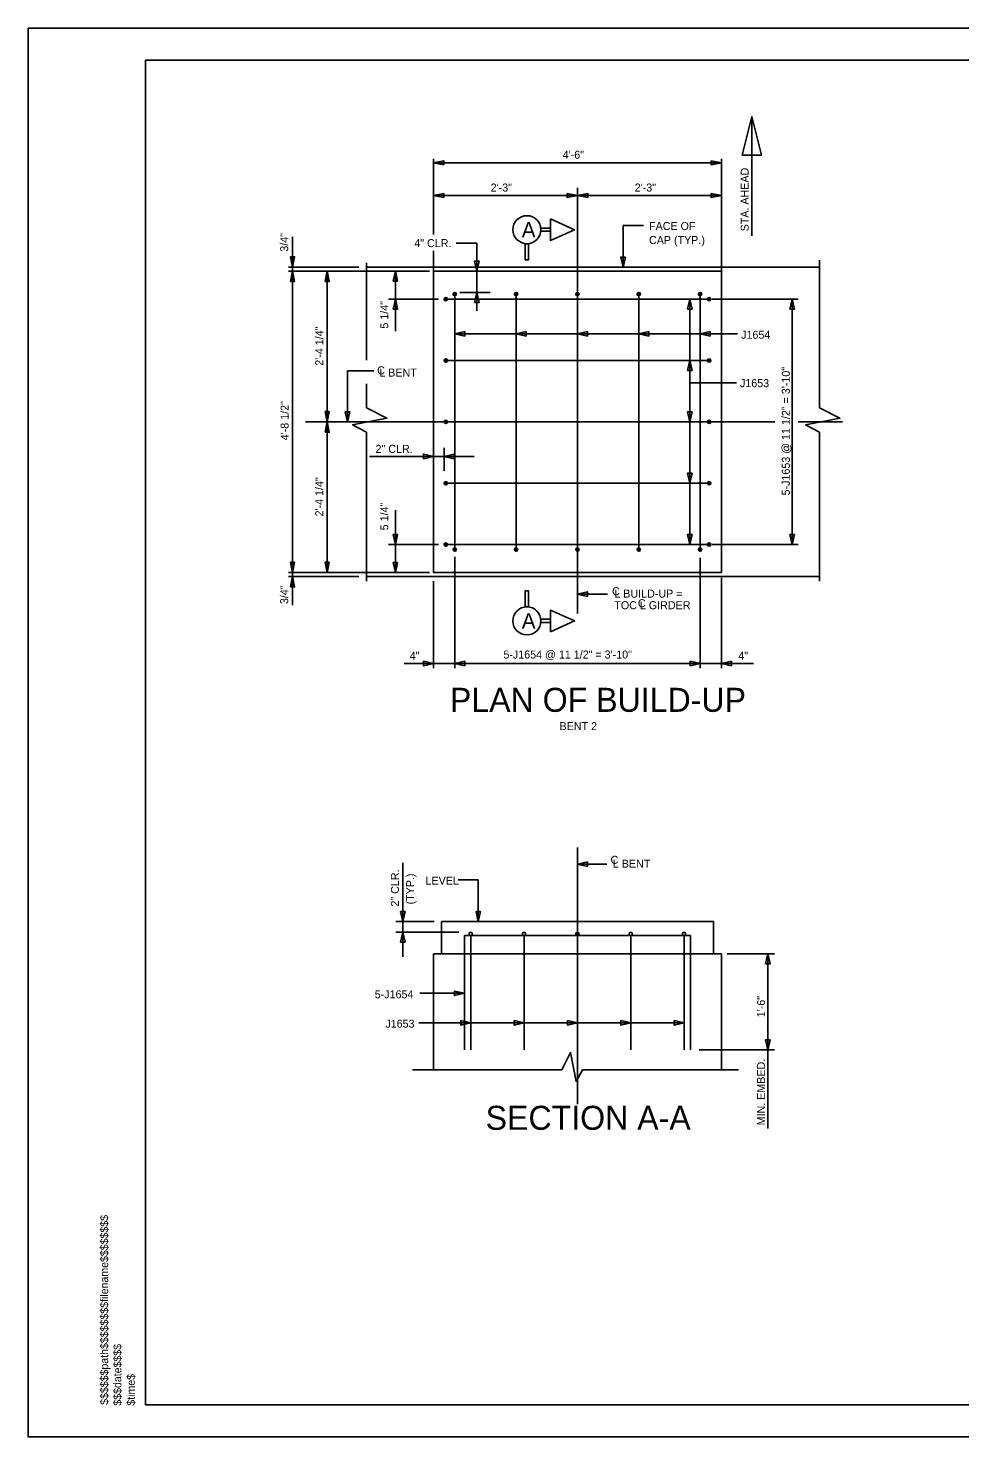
# Model space of a CAD drawing. Extents: x 1970675.2 to 1970711.3, y 796145.2 to 796167.2.
# Drawn here: x 1970675.24 to 1970689.79, y 796145.25 to 796167.25 of the extents above; entities that cross this region are included whole.
import ezdxf

# ---------------------------------------------------------------- set-up
doc = ezdxf.new("R2010")
doc.units = 0
for name, color, linetype in [('BR_AUTO DIMENSION', 7, 'Continuous'), ('BR_BORDER LINES', 7, 'Continuous'), ('BR_CENTER LINES', 7, 'Continuous'), ('BR_CONCRETE', 7, 'Continuous'), ('BR_REBAR', 7, 'Continuous'), ('BR_TEXT', 7, 'Continuous'), ('Default', 7, 'Continuous'), ('Level 31', 7, 'Continuous'), ('RD_SHT_ID', 7, 'Continuous')]:
    doc.layers.add(name, color=color, linetype=linetype)

msp = doc.modelspace()

# ---------------------------------------------------------------- linework, layer by layer
at = {"layer": 'BR_AUTO DIMENSION'}
for p, q in [((1970686.542, 796165.865), (1970686.542, 796164.002)), ((1970681.566, 796164.025), (1970681.566, 796165.207)), ((1970686.066, 796163.452), (1970686.066, 796165.207)), ((1970681.566, 796165.145), (1970686.066, 796165.145)), ((1970683.816, 796164.751), (1970683.816, 796164.386)), ((1970681.566, 796164.632), (1970683.816, 796164.632)), ((1970686.066, 796164.632), (1970683.816, 796164.632)), ((1970684.53, 796164.165), (1970684.53, 796163.515)), ((1970684.53, 796164.165), (1970684.847, 796164.165)), ((1970679.367, 796163.452), (1970679.367, 796163.985)), ((1970682.246, 796163.89), (1970681.922, 796163.89)), ((1970682.246, 796162.831), (1970682.246, 796163.89)), ((1970681.566, 796163.452), (1970681.566, 796163.771)), ((1970680.402, 796163.515), (1970679.301, 796163.515)), ((1970681.504, 796163.452), (1970679.305, 796163.452)), ((1970679.367, 796158.744), (1970679.367, 796163.452)), ((1970679.909, 796163.452), (1970679.909, 796161.098)), ((1970680.972, 796163.452), (1970680.972, 796162.513)), ((1970681.645, 796163.015), (1970680.865, 796163.015)), ((1970681.978, 796163.119), (1970682.453, 796163.119)), ((1970685.57, 796163.015), (1970685.57, 796159.181)), ((1970685.921, 796163.015), (1970687.264, 796163.015)), ((1970687.172, 796159.181), (1970687.172, 796163.015)), ((1970681.9, 796162.474), (1970686.315, 796162.474)), ((1970680.223, 796161.897), (1970680.223, 796161.098)), ((1970680.635, 796161.897), (1970680.223, 796161.897)), ((1970685.57, 796161.705), (1970686.299, 796161.705)), ((1970679.852, 796161.098), (1970679.988, 796161.098)), ((1970679.909, 796161.098), (1970679.909, 796158.744)), ((1970682.202, 796160.558), (1970680.567, 796160.558)), ((1970681.733, 796160.69), (1970681.733, 796160.334)), ((1970680.972, 796158.744), (1970680.972, 796159.718)), ((1970681.645, 796159.181), (1970680.865, 796159.181)), ((1970685.921, 796159.181), (1970687.264, 796159.181)), ((1970681.9, 796158.988), (1970681.9, 796157.249)), ((1970685.733, 796158.975), (1970685.733, 796157.249)), ((1970680.402, 796158.681), (1970679.301, 796158.681)), ((1970681.504, 796158.744), (1970679.305, 796158.744)), ((1970679.367, 796158.744), (1970679.367, 796158.233)), ((1970681.566, 796158.61), (1970681.566, 796157.249)), ((1970686.066, 796158.661), (1970686.066, 796157.249)), ((1970683.816, 796158.408), (1970684.288, 796158.408)), ((1970681.11, 796157.324), (1970686.568, 796157.324)), ((1970681.088, 796154.21), (1970681.088, 796152.745)), ((1970683.816, 796154.19), (1970684.276, 796154.19)), ((1970681.951, 796153.943), (1970682.268, 796153.943)), ((1970682.268, 796153.943), (1970682.268, 796153.293)), ((1970681.577, 796153.293), (1970680.978, 796153.293)), ((1970681.966, 796153.126), (1970680.978, 796153.126)), ((1970686.154, 796152.792), (1970686.897, 796152.792)), ((1970686.791, 796152.792), (1970686.791, 796150.062)), ((1970682.051, 796152.173), (1970681.356, 796152.173)), ((1970685.483, 796151.714), (1970681.338, 796151.714)), ((1970681.733, 796151.714), (1970681.653, 796151.714)), ((1970682.983, 796151.714), (1970682.903, 796151.714)), ((1970683.816, 796151.714), (1970683.736, 796151.714)), ((1970684.15, 796151.714), (1970684.069, 796151.714)), ((1970684.65, 796151.714), (1970684.569, 796151.714)), ((1970685.483, 796151.714), (1970685.403, 796151.714)), ((1970685.717, 796151.292), (1970686.897, 796151.292))]:
    msp.add_line(p, q, dxfattribs=at)
for points in [[(1970681.729, 796165.113), (1970681.566, 796165.145), (1970681.729, 796165.176)], [(1970685.904, 796165.176), (1970686.066, 796165.145), (1970685.904, 796165.113)], [(1970681.729, 796164.601), (1970681.566, 796164.632), (1970681.729, 796164.664)], [(1970683.654, 796164.664), (1970683.816, 796164.632), (1970683.654, 796164.601)], [(1970683.979, 796164.601), (1970683.816, 796164.632), (1970683.979, 796164.664)], [(1970685.904, 796164.664), (1970686.066, 796164.632), (1970685.904, 796164.601)], [(1970679.336, 796163.677), (1970679.367, 796163.515), (1970679.398, 796163.677)], [(1970684.566, 796163.671), (1970684.53, 796163.515), (1970684.494, 796163.671)], [(1970679.336, 796163.29), (1970679.367, 796163.452), (1970679.398, 796163.29)], [(1970679.878, 796163.29), (1970679.909, 796163.452), (1970679.94, 796163.29)], [(1970681.008, 796163.296), (1970680.972, 796163.452), (1970680.936, 796163.296)], [(1970682.282, 796163.608), (1970682.246, 796163.452), (1970682.21, 796163.608)], [(1970681.008, 796162.859), (1970680.972, 796163.015), (1970680.936, 796162.859)], [(1970682.21, 796162.963), (1970682.246, 796163.119), (1970682.282, 796162.963)], [(1970685.534, 796162.859), (1970685.57, 796163.015), (1970685.606, 796162.859)], [(1970687.136, 796162.859), (1970687.172, 796163.015), (1970687.208, 796162.859)], [(1970682.056, 796162.51), (1970681.9, 796162.474), (1970682.056, 796162.438)], [(1970683.014, 796162.51), (1970682.858, 796162.474), (1970683.014, 796162.438)], [(1970683.972, 796162.51), (1970683.816, 796162.474), (1970683.972, 796162.438)], [(1970684.931, 796162.51), (1970684.775, 796162.474), (1970684.931, 796162.438)], [(1970685.889, 796162.51), (1970685.733, 796162.474), (1970685.889, 796162.438)], [(1970685.534, 796161.9), (1970685.57, 796162.056), (1970685.606, 796161.9)], [(1970679.94, 796161.26), (1970679.909, 796161.098), (1970679.878, 796161.26)], [(1970680.259, 796161.254), (1970680.223, 796161.098), (1970680.187, 796161.254)], [(1970685.606, 796161.254), (1970685.57, 796161.098), (1970685.534, 796161.254)], [(1970679.878, 796160.935), (1970679.909, 796161.098), (1970679.94, 796160.935)], [(1970681.41, 796160.522), (1970681.566, 796160.558), (1970681.41, 796160.594)], [(1970681.889, 796160.594), (1970681.733, 796160.558), (1970681.889, 796160.522)], [(1970685.606, 796160.296), (1970685.57, 796160.14), (1970685.534, 796160.296)], [(1970681.008, 796159.337), (1970680.972, 796159.181), (1970680.936, 796159.337)], [(1970685.606, 796159.337), (1970685.57, 796159.181), (1970685.534, 796159.337)], [(1970687.208, 796159.337), (1970687.172, 796159.181), (1970687.136, 796159.337)], [(1970679.398, 796158.906), (1970679.367, 796158.744), (1970679.336, 796158.906)], [(1970679.94, 796158.906), (1970679.909, 796158.744), (1970679.878, 796158.906)], [(1970681.008, 796158.9), (1970680.972, 796158.744), (1970680.936, 796158.9)], [(1970679.336, 796158.519), (1970679.367, 796158.681), (1970679.398, 796158.519)], [(1970683.972, 796158.372), (1970683.816, 796158.408), (1970683.972, 796158.444)], [(1970681.41, 796157.36), (1970681.566, 796157.324), (1970681.41, 796157.288)], [(1970682.056, 796157.288), (1970681.9, 796157.324), (1970682.056, 796157.36)], [(1970685.577, 796157.36), (1970685.733, 796157.324), (1970685.577, 796157.288)], [(1970686.222, 796157.36), (1970686.066, 796157.324), (1970686.222, 796157.288)], [(1970683.972, 796154.154), (1970683.816, 796154.19), (1970683.972, 796154.226)], [(1970681.124, 796153.449), (1970681.088, 796153.293), (1970681.052, 796153.449)], [(1970682.304, 796153.449), (1970682.268, 796153.293), (1970682.232, 796153.449)], [(1970681.052, 796152.97), (1970681.088, 796153.126), (1970681.124, 796152.97)], [(1970686.755, 796152.636), (1970686.791, 796152.792), (1970686.827, 796152.636)], [(1970681.895, 796152.209), (1970682.051, 796152.173), (1970681.895, 796152.137)], [(1970681.994, 796151.75), (1970682.15, 796151.714), (1970681.994, 796151.678)], [(1970682.827, 796151.75), (1970682.983, 796151.714), (1970682.827, 796151.678)], [(1970683.66, 796151.75), (1970683.816, 796151.714), (1970683.66, 796151.678)], [(1970684.494, 796151.75), (1970684.65, 796151.714), (1970684.494, 796151.678)], [(1970685.327, 796151.75), (1970685.483, 796151.714), (1970685.327, 796151.678)], [(1970686.827, 796151.448), (1970686.791, 796151.292), (1970686.755, 796151.448)]]:
    msp.add_lwpolyline(points, close=True, dxfattribs=at)
at = {"layer": 'BR_BORDER LINES'}
for p, q in [((1970710.736, 796166.746), (1970677.07, 796166.746)), ((1970677.07, 796145.746), (1970677.07, 796166.746)), ((1970677.07, 796145.746), (1970710.736, 796145.746))]:
    msp.add_line(p, q, dxfattribs=at)
at = {"layer": 'BR_CENTER LINES'}
for p, q in [((1970683.816, 796164.632), (1970683.816, 796158.104)), ((1970679.567, 796161.098), (1970686.901, 796161.098)), ((1970687.263, 796161.098), (1970687.959, 796161.098)), ((1970683.816, 796154.451), (1970683.816, 796150.443))]:
    msp.add_line(p, q, dxfattribs=at)
at = {"layer": 'BR_CONCRETE'}
for p, q in [((1970680.522, 796163.515), (1970687.596, 796163.515)), ((1970681.566, 796163.452), (1970681.566, 796158.744)), ((1970681.566, 796163.452), (1970686.066, 796163.452)), ((1970686.066, 796163.452), (1970686.066, 796158.744)), ((1970680.522, 796158.681), (1970687.596, 796158.681)), ((1970681.566, 796158.744), (1970686.066, 796158.744)), ((1970681.691, 796153.293), (1970681.691, 796152.792)), ((1970681.691, 796153.293), (1970685.941, 796153.293)), ((1970685.941, 796153.293), (1970685.941, 796152.792)), ((1970681.566, 796152.792), (1970681.566, 796150.98)), ((1970681.566, 796152.792), (1970686.066, 796152.792)), ((1970686.066, 796152.792), (1970686.066, 796150.98))]:
    msp.add_line(p, q, dxfattribs=at)
at = {"layer": 'BR_REBAR'}
for p, q in [((1970681.733, 796163.015), (1970685.9, 796163.015)), ((1970681.9, 796159.077), (1970681.9, 796163.119)), ((1970682.858, 796159.077), (1970682.858, 796163.119)), ((1970683.816, 796159.077), (1970683.816, 796163.119)), ((1970684.775, 796159.077), (1970684.775, 796163.119)), ((1970685.733, 796159.077), (1970685.733, 796163.119)), ((1970681.733, 796162.056), (1970685.9, 796162.056)), ((1970681.733, 796161.098), (1970685.9, 796161.098)), ((1970681.733, 796160.14), (1970685.9, 796160.14)), ((1970681.733, 796159.181), (1970685.9, 796159.181)), ((1970682.051, 796153.074), (1970682.051, 796151.292)), ((1970685.582, 796153.074), (1970682.051, 796153.074)), ((1970682.15, 796151.292), (1970682.15, 796153.074)), ((1970682.983, 796151.292), (1970682.983, 796153.074)), ((1970683.816, 796151.292), (1970683.816, 796153.074)), ((1970684.65, 796151.292), (1970684.65, 796153.074)), ((1970685.483, 796151.292), (1970685.483, 796153.074)), ((1970685.582, 796153.074), (1970685.582, 796151.292))]:
    msp.add_line(p, q, dxfattribs=at)
for centre, radius in [((1970681.759, 796163.015), 0.026), ((1970681.9, 796163.093), 0.0261), ((1970682.858, 796163.093), 0.0261), ((1970683.816, 796163.093), 0.0261), ((1970684.775, 796163.093), 0.0261), ((1970685.733, 796163.093), 0.0261), ((1970685.874, 796163.015), 0.026), ((1970681.759, 796162.056), 0.026), ((1970685.874, 796162.056), 0.026), ((1970681.759, 796161.098), 0.026), ((1970685.874, 796161.098), 0.026), ((1970681.759, 796160.14), 0.026), ((1970685.874, 796160.14), 0.026), ((1970681.759, 796159.181), 0.026), ((1970681.9, 796159.103), 0.0261), ((1970682.858, 796159.103), 0.0261), ((1970683.816, 796159.103), 0.0261), ((1970684.775, 796159.103), 0.0261), ((1970685.733, 796159.103), 0.0261), ((1970685.874, 796159.181), 0.026), ((1970682.15, 796153.1), 0.0261), ((1970682.983, 796153.1), 0.0261), ((1970683.816, 796153.1), 0.0261), ((1970684.65, 796153.1), 0.0261), ((1970685.483, 796153.1), 0.0261)]:
    msp.add_circle(centre, radius, dxfattribs=at)
at = {"layer": 'BR_TEXT'}
for points in [[(1970683.246, 796164.074), (1970683.396, 796164.074), (1970683.396, 796164.124), (1970683.246, 796164.124)], [(1970683.396, 796164.267), (1970683.772, 796164.099), (1970683.396, 796163.93)], [(1970683.002, 796163.629), (1970683.052, 796163.629), (1970683.052, 796163.88), (1970683.002, 796163.88)], [(1970683.002, 796158.458), (1970683.052, 796158.458), (1970683.052, 796158.208), (1970683.002, 796158.208)], [(1970683.396, 796157.82), (1970683.772, 796157.989), (1970683.396, 796158.158)], [(1970683.246, 796158.014), (1970683.396, 796158.014), (1970683.396, 796157.964), (1970683.246, 796157.964)]]:
    msp.add_lwpolyline(points, close=True, dxfattribs=at)
for centre in [(1970683.027, 796164.099), (1970683.027, 796157.989)]:
    msp.add_circle(centre, 0.219, dxfattribs=at)
at = {"layer": 'Default'}
for p, q in [((1970687.596, 796163.622), (1970687.596, 796161.319)), ((1970680.522, 796163.583), (1970680.522, 796162.063)), ((1970680.522, 796161.692), (1970680.522, 796161.319)), ((1970680.522, 796160.936), (1970680.522, 796158.609)), ((1970687.596, 796160.936), (1970687.596, 796158.609)), ((1970681.24, 796150.98), (1970683.571, 796150.98)), ((1970683.894, 796150.98), (1970686.333, 796150.98))]:
    msp.add_line(p, q, dxfattribs=at)
msp.add_lwpolyline([(1970686.692, 796165.265), (1970686.542, 796165.865), (1970686.392, 796165.265)], close=True, dxfattribs=at)
for points in [[(1970680.522, 796160.936), (1970680.305, 796161.054), (1970680.841, 796161.154), (1970680.522, 796161.319)], [(1970687.596, 796160.936), (1970687.38, 796161.054), (1970687.916, 796161.154), (1970687.596, 796161.319)], [(1970683.894, 796150.98), (1970683.795, 796150.797), (1970683.71, 796151.25), (1970683.571, 796150.98)]]:
    msp.add_lwpolyline(points, dxfattribs=at)
at = {"layer": 'Level 31'}
msp.add_line((1970711.236, 796167.246), (1970675.236, 796167.246), dxfattribs=at)
msp.add_lwpolyline([(1970675.236, 796167.246), (1970675.236, 796145.246), (1970711.236, 796145.246), (1970711.236, 796167.246)], dxfattribs=at)

# ---------------------------------------------------------------- texts
at = {"layer": 'BR_AUTO DIMENSION'}
for s, p in [('4\'-6"', (1970683.586, 796165.207)), ('2\'-3"', (1970682.461, 796164.695)), ('2\'-3"', (1970684.711, 796164.695)), ('FACE OF', (1970684.935, 796164.094)), ('4" CLR.', (1970681.268, 796163.827)), ('CAP (TYP.)', (1970684.935, 796163.875)), ('J1654', (1970686.374, 796162.396)), ('J1653', (1970686.355, 796161.64)), ('2" CLR.', (1970680.663, 796160.614)), ('C', (1970684.358, 796158.39)), ('C', (1970684.358, 796158.39)), ('L BUILD-UP = ', (1970684.393, 796158.353)), ('TOC L GIRDER', (1970684.393, 796158.172)), ('C', (1970684.761, 796158.203)), ('5-J1654 @ 11 1/2" = 3\'-10"', (1970682.66, 796157.402)), ('BENT 2', (1970683.537, 796156.283))]:
    msp.add_text(s, height=0.125, dxfattribs=at).set_placement(p)
for s, rotation, p in [('STA. AHEAD', 90, (1970686.491, 796164.073)), ('2\'-4 1/4"', 90, (1970679.846, 796161.975)), ('5-J1653 @ 11 1/2" = 3\'-10"', 90, (1970687.134, 796159.949)), ('4\'-8 1/2"', 90, (1970679.305, 796160.81)), ('2\'-4 1/4"', 90, (1970679.846, 796159.621)), ('4"', 360, (1970681.196, 796157.382)), ('4"', 360, (1970686.33, 796157.382)), ('C', 360, (1970684.334, 796154.195)), ('L BENT', 360, (1970684.369, 796154.135)), ('2" CLR.', 90, (1970681.028, 796153.528)), ('(TYP.)', 90, (1970681.265, 796153.561)), ('LEVEL', 360, (1970681.444, 796153.87)), ('5-J1654', 360, (1970680.65, 796152.095)), ('1\'-6"', 90, (1970686.747, 796151.799)), ('J1653', 360, (1970680.816, 796151.636)), ('MIN. EMBED.', 90, (1970686.747, 796150.111))]:
    msp.add_text(s, height=0.125, rotation=rotation, dxfattribs=at).set_placement(p)
at = {"layer": 'BR_TEXT'}
for s, height, p in [('A', 0.24, (1970682.947, 796163.979)), ('A', 0.24, (1970682.947, 796157.869)), ('PLAN OF BUILD-UP', 0.375, (1970681.824, 796156.569))]:
    msp.add_text(s, height=height, dxfattribs=at).set_placement(p)
for s, height, rotation, p in [('3/4"', 0.125, 90, (1970679.298, 796163.755)), ('5 1/4"', 0.125, 90, (1970680.862, 796162.554)), ('C', 0.125, 360, (1970680.688, 796161.84)), ('L BENT', 0.125, 360, (1970680.722, 796161.805)), ('5 1/4"', 0.125, 90, (1970680.862, 796159.404)), ('3/4"', 0.125, 90, (1970679.298, 796158.252)), ('SECTION A-A', 0.375, 360, (1970682.382, 796150.041))]:
    msp.add_text(s, height=height, rotation=rotation, dxfattribs=at).set_placement(p)
at = {"layer": 'RD_SHT_ID'}
for s, height, p in [('$$$$$$path$$$$$$$$filename$$$$$$$$', 0.12347, (1970676.486, 796145.746)), ('$$$date$$$$', 0.12347, (1970676.692, 796145.733)), ('$time$', 0.1235, (1970676.903, 796145.733))]:
    msp.add_text(s, height=height, rotation=90, dxfattribs=at).set_placement(p)

doc.saveas('drawing.dxf')
